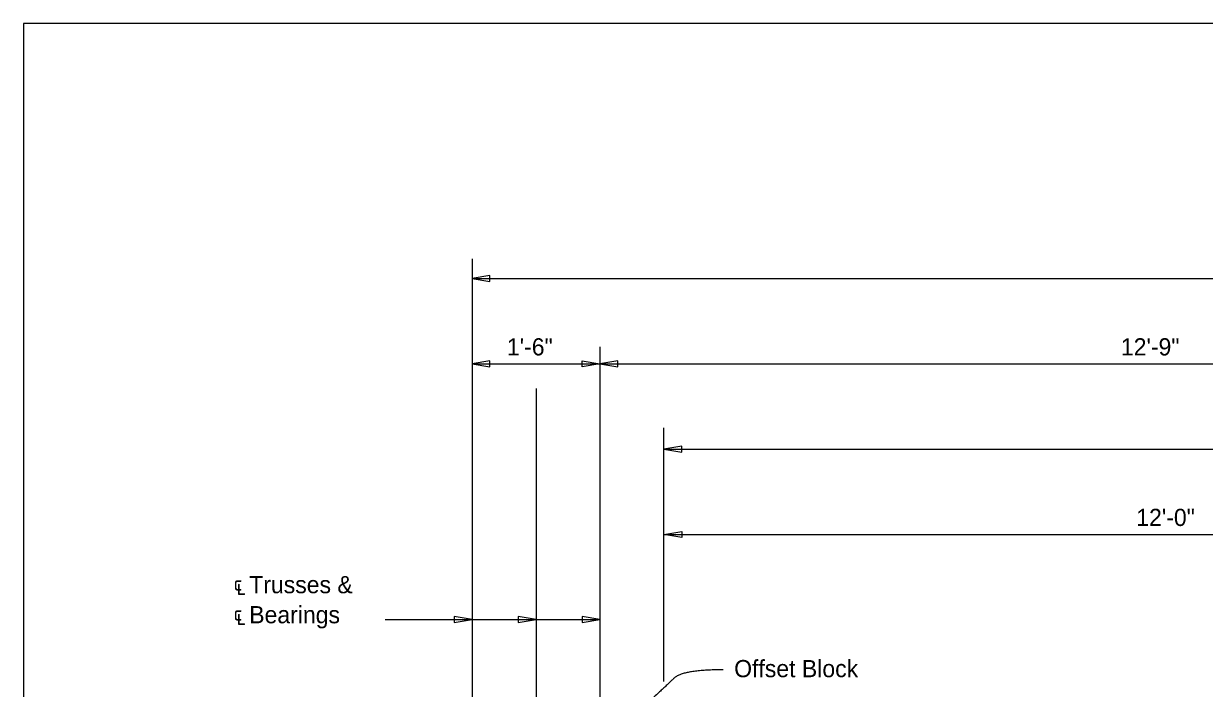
# Model space of a CAD drawing. Extents: x 11137.4 to 11208.2, y 76297.7 to 76332.4.
# Drawn here: x 11137.44 to 11151.28, y 76324.37 to 76332.16 of the extents above; entities that cross this region are included whole.
import ezdxf

# ---------------------------------------------------------------- set-up
doc = ezdxf.new("R2010")
doc.units = 0
for name, color, linetype in [('ActivePts-ConstElements', 7, 'Continuous'), ('CL_Minor', 7, 'Continuous'), ('Dimension', 7, 'Continuous'), ('TextStructures', 7, 'Continuous')]:
    doc.layers.add(name, color=color, linetype=linetype)

msp = doc.modelspace()

# ---------------------------------------------------------------- linework, layer by layer
at = {"layer": 'ActivePts-ConstElements'}
msp.add_lwpolyline([(11137.439, 76306.213), (11178.49, 76306.213), (11178.49, 76332.159), (11137.439, 76332.159)], close=True, dxfattribs=at)
at = {"layer": 'CL_Minor'}
for p, q in [((11142.696, 76329.402), (11142.696, 76317.017)), ((11144.196, 76328.372), (11144.196, 76317.017)), ((11143.446, 76327.885), (11143.446, 76316.93))]:
    msp.add_line(p, q, dxfattribs=at)
at = {"layer": 'Dimension'}
for p, q in [((11142.696, 76329.171), (11171.196, 76329.171)), ((11142.696, 76328.171), (11171.196, 76328.171)), ((11144.946, 76324.45), (11144.946, 76327.424)), ((11144.946, 76327.171), (11168.946, 76327.171)), ((11144.946, 76326.171), (11168.946, 76326.171)), ((11141.676, 76325.177), (11144.196, 76325.177))]:
    msp.add_line(p, q, dxfattribs=at)
for points in [[(11142.696, 76329.171), (11142.904, 76329.136), (11142.904, 76329.206)], [(11142.696, 76328.171), (11142.904, 76328.136), (11142.904, 76328.206)], [(11144.196, 76328.171), (11143.987, 76328.136), (11143.987, 76328.206)], [(11144.196, 76328.171), (11144.404, 76328.136), (11144.404, 76328.206)], [(11144.946, 76327.171), (11145.154, 76327.136), (11145.154, 76327.206)], [(11145.154, 76326.136), (11144.946, 76326.171), (11145.154, 76326.206)], [(11142.696, 76325.177), (11142.487, 76325.212), (11142.487, 76325.141)], [(11143.446, 76325.177), (11143.237, 76325.212), (11143.237, 76325.141)], [(11144.196, 76325.177), (11143.987, 76325.212), (11143.987, 76325.141)]]:
    msp.add_lwpolyline(points, close=True, dxfattribs=at)
msp.add_open_spline([(11145.64, 76324.587), (11145.165, 76324.587), (11144.963, 76324.389), (11144.606, 76324.066)], degree=2, dxfattribs=at)

# ---------------------------------------------------------------- texts
for s, p in [('12\'-0"', (11150.483, 76326.272)), ('℄ Trusses & ', (11139.9, 76325.484)), ('℄ Bearings ', (11139.9, 76325.132))]:
    msp.add_text(s, height=0.2016, dxfattribs=at).set_placement(p)
at = {"layer": 'TextStructures'}
for s, p in [('1\'-6"', (11143.105, 76328.271)), ('12\'-9"', (11150.303, 76328.271)), ('Offset Block', (11145.769, 76324.5))]:
    msp.add_text(s, height=0.2016, dxfattribs=at).set_placement(p)

doc.saveas('drawing.dxf')
